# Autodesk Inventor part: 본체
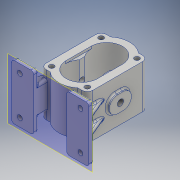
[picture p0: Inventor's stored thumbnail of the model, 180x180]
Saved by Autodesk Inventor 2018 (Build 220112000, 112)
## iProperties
Created: 2023-06
Part Number: 본체
Material: 알루미늄 6061
Document SubType Name: Modeling
Designer: home
Density: 2.7 g/cm^3
Appearance: 알루미늄 - 평지
Mass: 1294.82 g
Surface Area: 981.507 cm^2
Volume: 479.562 cm^3
Author: home
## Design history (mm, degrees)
sketch "스케치1"
  geometry: L1 (42.5, 45)-(42.5, -45); L2 (-42.5, -45)-(-42.5, 45); L3 (-42.5, 55)-(42.5, -55); L4 (42.5, 55)-(-42.5, -55); L5 (-32.5, 55)-(-25.278, 55); L6 (25.278, 55)-(32.5, 55); L7 (32.5, -55)-(25.278, -55); L8 (-25.278, -55)-(-32.5, -55); A1 r 40 centre (0, 24) between (25.278, 55) and (-25.278, 55); A2 r 40 centre (0, -24) between (-25.278, -55) and (25.278, -55); A3 r 10 centre (-32.5, 45) between (-32.5, 55) and (-42.5, 45); A4 r 10 centre (32.5, 45) between (42.5, 45) and (32.5, 55); A5 r 10 centre (32.5, -45) between (32.5, -55) and (42.5, -45); A6 r 10 centre (-32.5, -45) between (-42.5, -45) and (-32.5, -55); 1 further point
  constraints: 16 end point, 12 point on circle, 10 tangent, 6 centre point, 5 parallel, 4 equal radius, 4 point on line, 2 horizontal, 2 midpoint, 2 perpendicular
  dimensions: "d0" = 85 distance of L3.end L4.end; "d1" = 110 distance of L4.start L3.end; "d7" = 10 radius of A3; "d8" = 40 radius of A1; "d9" = 37.6942 deg angle of L1 L4; "d10" = 37.6942 deg angle of L3 L1; "d11" = 110 distance between parallel lines of L6 L7; "d12" = 55 distance from line of point (0, 0) L6; "d13" = 17.22155 distance from line of L6.start L1; "d14" = 17.22155 distance from line of L7.end L1; "d15" = 42.5 distance from line of A1.centre L1; "d16" = 42.5 distance from line of A2.centre L1
extrude "돌출1" new body sketch "스케치1" stored distance "d17" = 79; taper "d18" = 0 deg
sketch "스케치2"
  geometry: L1 (-42.5, 45)-(-42.5, -45) reference; L2 (-42.5, 0)-(42.5, 0); L3 (42.5, 45)-(42.5, -45) reference; L4 (-22.5, 5)-(-22.5, -5); L5 (22.5, 5)-(22.5, -5); A1 r 28.5 centre (0, -22.493) between (-22.5, -5) and (22.5, -5); A2 r 28.5 centre (0, 22.493) between (22.5, 5) and (-22.5, 5); 2 further points
  constraints: 6 end point, 4 point on circle, 3 midpoint, 2 centre point, 2 vertical alignment, 1 parallel, 1 vertical
  dimensions: "d21" = 28.5 radius of A1; "d22" = 28.5 radius of A2; "d26" = 45 distance from line of L4.start L5; "d27" = 65 distance between parallel lines of L3 L4; "d32" = 5 distance from line of L5.start L2; "d33" = 5 distance from line of L5.end L2
extrude "돌출2" cut sketch "스케치2" distance "d34" = 79; taper "d35" = 0 deg
sketch "스케치3"
  geometry: C1 r 4.5 at (-32.5, 45); C2 r 4.5 at (32.5, 45); C3 r 4.5 at (-32.5, -45); C4 r 4.5 at (32.5, -45); A1 r 10 centre (-32.5, 45) between (-32.5, 55) and (-42.5, 45) reference; A2 r 10 centre (32.5, 45) between (42.5, 45) and (32.5, 55) reference; A3 r 10 centre (-32.5, -45) between (-42.5, -45) and (-32.5, -55) reference; A4 r 10 centre (32.5, -45) between (32.5, -55) and (42.5, -45) reference; 1 further point
  constraints: 4 centre point, 4 coincident
  dimensions: "d37" = 9 diameter of C1; "d38" = 9 diameter of C2; "d39" = 9 diameter of C3; "d40" = 9 diameter of C4
extrude "돌출3" cut sketch "스케치3" distance "d41" = 79; taper "d42" = 0 deg
node "작업 평면2"
sketch "스케치5"
  geometry: L1 (65, -50)-(35, -50); L2 (30, -45)-(30, 45); L3 (35, 50)-(65, 50); L4 (70, 45)-(70, -45); L5 (70, -50)-(30, 50); L6 (30, -50)-(70, 50); L7 (-35, -50)-(-65, -50); L8 (-70, -45)-(-70, 45); L9 (-65, 50)-(-35, 50); L10 (-30, 45)-(-30, -45); L11 (-30, -50)-(-70, 50); L12 (-70, -50)-(-30, 50); A1 r 5 centre (65, -45) between (65, -50) and (70, -45); A2 r 5 centre (35, -45) between (30, -45) and (35, -50); A3 r 5 centre (-35, -45) between (-35, -50) and (-30, -45); A4 r 5 centre (-65, -45) between (-70, -45) and (-65, -50); A5 r 5 centre (-35, 45) between (-30, 45) and (-35, 50); A6 r 5 centre (-65, 45) between (-65, 50) and (-70, 45); A7 r 5 centre (35, 45) between (35, 50) and (30, 45); A8 r 5 centre (65, 45) between (70, 45) and (65, 50); 3 further points
  constraints: 24 end point, 17 tangent, 16 point on circle, 16 point on line, 8 centre point, 7 equal radius, 4 midpoint, 4 parallel, 2 horizontal, 2 perpendicular
  dimensions: "d48" = 40 distance of L5.end L6.end; "d49" = 100 distance of L6.start L5.end; "d50" = 40 distance of L11.end L12.end; "d51" = 100 distance of L12.start L11.end; "d52" = 5 radius of A1; "d55" = 50 distance from line of point (0, 0) L3; "d69" = 70 distance from line of L8 point (0, 0); "d70" = 70 distance from line of L4 point (0, 0)
extrude "돌출4" join sketch "스케치5" distance "d56" = 9; taper "d57" = 0 deg
sketch "스케치7"
  geometry: C1 r 9 at (-55, 35); C2 r 9 at (55, 35); C3 r 9 at (55, -35); C4 r 9 at (-55, -35); 1 further point
  constraints: 4 centre point, 1 horizontal alignment, 1 vertical alignment
  dimensions: "d58" = 18 diameter of C1; "d59" = 18 diameter of C2; "d60" = 18 diameter of C3; "d61" = 18 diameter of C4; "d62" = 110 distance of C2.centre C1.centre; "d63" = 70 distance of C3.centre C2.centre; "d64" = 110 distance of C3.centre C4.centre; "d65" = 70 distance of C4.centre C1.centre; "d66" = 55 horizontal distance of C2.centre point (0, 0); "d67" = 35 vertical distance of C3.centre point (0, 0)
extrude "돌출5" join sketch "스케치7" distance "d71" = 2; taper "d72" = 0 deg
sketch "스케치8"
  geometry: L1 (-30, 21)-(-30, -21); L2 (-38, 21)-(-38, -21); L3 (-30, -21)-(-30, 21); A1 r 4 centre (-34, 21) between (-30, 21) and (-38, 21); A2 r 4 centre (-34, -21) between (-38, -21) and (-30, -21); 4 further points
  constraints: 8 end point, 6 point on circle, 4 tangent, 2 centre point, 2 coincident, 2 midpoint, 1 parallel, 1 vertical
  dimensions: "d75" = 50 dimension on A2 A1
extrude "돌출6" join sketch "스케치8" stored distance "d91" = 9; taper "d92" = 0 deg
node "작업 평면3"
sketch "스케치10"
  geometry: L1 (-62, -71)-(-34.15, -5.39); 1 further point
  constraints: 2 end point
feature "리브1" sketch "스케치10" dims "d101" = 1, "d102" = 7, "d103" = 0, "d104" = 0, "d105" = 1, "d106" = 1
node "작업 평면4"
sketch "스케치11"
  geometry: L1 (20, 0)-(-20, 0); L2 (5, 15)-(-5, 15); L3 (-5, -15)-(5, -15); A1 r 15 centre (5, 0) between (5, -15) and (5, 15); A2 r 15 centre (-5, 0) between (-5, 15) and (-5, -15); 2 further points
  constraints: 8 end point, 6 point on circle, 4 tangent, 2 centre point, 2 point on line, 1 coincident, 1 horizontal, 1 midpoint, 1 parallel
  dimensions: "d108" = 40 distance of L1.start L1.end; "d109" = 30 diameter of A2
extrude "돌출7" join sketch "스케치11" stored distance "d110" = 9; taper "d111" = 0 deg
sketch "스케치17"
  geometry: L1 (0, 10)-(0, 55.993) reference; L2 (0, 29)-(4.5, 29); L3 (4.5, 29)-(4.5, -19); L4 (4.5, -19)-(0, -19); L5 (0, -19)-(0, 29); 2 further points
  constraints: 8 end point, 2 parallel, 1 horizontal, 1 horizontal alignment, 1 midpoint, 1 perpendicular, 1 point on line
  dimensions: "d124" = 4.5 distance of L3.end L4.end; "d125" = 48 distance of L2.end L3.end
extrude "돌출10" cut sketch "스케치17" distance "d126" = 6; taper "d127" = 0 deg
node "작업 평면7"
  node "작업 평면6"
sketch "스케치18"
  geometry: 2 further points
  constraints: 1 vertical alignment, 1 other
  dimensions: "d130" = 20 distance of point (-50, 30) point (-50, 50)
feature "엠보싱1" sketch "스케치18" dims "d0" = 85, "d1" = 110, "d7" = 10, "d8" = 40, "d9" = 6.57889, "d10" = 6.57889, "d11" = 110, "d12" = 55, "d13" = 17.22155, "d14" = 17.22155, "d15" = 42.5, "d16" = 42.5, "d131" = 0.5, "d132" = 0
sketch "스케치19"
  geometry: C1 r 9 at (0, 0) reference; C2 r 4.5 at (0, 0); C3 r 9 at (0, -70) reference; C4 r 4.5 at (0, -70); C5 r 9 at (-110, -70) reference; C6 r 4.5 at (-110, -70); C7 r 9 at (-110, 0) reference; C8 r 4.5 at (-110, 0); 1 further point
  constraints: 4 centre point, 4 coincident
  dimensions: "d133" = 9 diameter of C2; "d134" = 9 diameter of C4; "d135" = 9 diameter of C6; "d136" = 9 diameter of C8
extrude "돌출11" cut sketch "스케치19" extent not by distance; stored distance "d137" = 6; taper "d138" = 0 deg
fillet "모깎기1" dims "d139" = 3
sketch "스케치20"
  geometry: 2 further points
  constraints: 1 coincident
hole "구멍1" sketch "스케치20" at (15, 5) diameter "d140" = 10.5; stored, may be unused: countersink angle "d146" = 90 deg, drill point angle "d148" = 0 deg; dims "d141" = 11, "d142" = 0.62479, "d143" = 10.589, "d144" = 4, "d145" = 2, "d147" = 17.5
node "솔리드1"
mirror "미러1"
mirror "미러2"
mirror "미러3"
mirror "미러4"
mirror "미러5"
mirror "미러6"
other parameters: "d98" = -14.5, "d107" = -47.5, "d129" = 144
